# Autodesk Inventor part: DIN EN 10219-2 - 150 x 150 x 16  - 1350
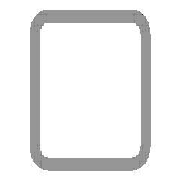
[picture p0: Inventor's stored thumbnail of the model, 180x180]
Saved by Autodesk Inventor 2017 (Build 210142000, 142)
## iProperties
_CCFamilyMember: 76
_CCFamilyDisplayName: DIN EN 10219-2 (Square Hollow Section - Cold Formed) - Cold formed welded structural hollow sections of non-alloy and fine grain structural steel
_FrameMemberDoc: Frame Member File
_Version: 15.0.0
_GetPNFromCC: 1
Created: 2017-11
Part Number: DIN EN 10219-2 - 150 x 150 x 16  - 1350
Material: Steel, Mild
Description: Cold formed welded structural hollow sections of non-alloy and fine grain structural steel
Document SubType Name: Modeling
Standard: DIN
Designer: iusti
Standard Revision: 2006-07
Standards Organization: DIN
Language: en-US
Size Designation: 150 x 150 x 16
Categories: <MemberInstance><Categories><Category DisplayName="Structural Shapes" InternalName="089c4875-fa83-4c05-b084-43b9cc11f5ed" Mnemonic="GRDR"><CategoryParameter Dis
Stock Number: 150 x 150 x 16
Mass: 79240 g
Surface Area: 12767.4 cm^2
Volume: 10094.3 cm^3
Density: 7.85 g/cm^3
Appearance: Semi-Polished
IsCustomPart: 1
G_L: 1350.000 mm
G_W: 150.000 mm
G_H: 150.000 mm
+6716C19D-968C-41AC-94F2-3194A5FEB298+CUTDETAIL1: Cut
+49856AF1-55B6-4B33-98D5-46D5E76A574D+CUTDETAIL2: Cut
Author: iusti
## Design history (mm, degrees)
node "Start plane"
node "End plane"
sketch "Sketch"
  geometry: L1 (-75, -27)-(-75, 27); L2 (-27, 75)-(27, 75); L3 (75, 27)-(75, -27); L4 (27, -75)-(-27, -75); L5 (-27, 59)-(27, 59); L6 (59, 27)-(59, -27); L7 (27, -59)-(-27, -59); L8 (-59, -27)-(-59, 27); L9 (0, 118.918)-(0, -118.918) reference; L10 (-118.918, 0)-(118.918, 0) reference; A1 r 48 centre (-27, -27) between (-75, -27) and (-27, -75); A2 r 48 centre (-27, 27) between (-27, 75) and (-75, 27); A3 r 48 centre (27, 27) between (75, 27) and (27, 75); A4 r 48 centre (27, -27) between (27, -75) and (75, -27); A5 r 32 centre (-27, 27) between (-27, 59) and (-59, 27); A6 r 32 centre (27, 27) between (59, 27) and (27, 59); A7 r 32 centre (27, -27) between (27, -59) and (59, -27); A8 r 32 centre (-27, -27) between (-59, -27) and (-27, -59)
  constraints: 16 end point, 16 point on circle, 8 centre point, 8 tangent, 4 parallel, 3 equal radius, 2 perpendicular, 7 other
  dimensions: "d7" = 48 radius of A1 (= G_IR); "d10" = 150 distance between parallel lines of L2 L4 (= G_H); "d11" = 150 distance between parallel lines of L1 L3 (= G_W); "d12" = 16 distance between parallel lines of L3 L6 (= G_T); "d15" = 75 distance between parallel lines of L2 L10 (= 0.5 x d10); "d16" = 75 distance between parallel lines of L9 L3 (= 0.5 x d11)
extrude "Body" new body sketch "Sketch" stored distance "d3" = 1350 (= G_L); taper "d4" = 0 deg
node "Driven Length"
  sketch "Sketch3"
    geometry: L1 (0, 0)-(10, 0) reference
    constraints: 2 end point, 1 horizontal
  workplane "Work Plane3"
  sketch "Sketch4"
    geometry: L1 (-2, 75)-(12, 75) reference; L2 (-2, 1425)-(12, 1425) reference
    dimensions: "d18" = 1350 distance between parallel lines of L1 L2 (derived)
workplane "Work Plane4"
split "Split1"
workplane "Work Plane5"
split "Split2"
body "Solid1"
other parameters: "G_W" = 150 [user parameter; used in 1 equation term], "G_H" = 150 [user parameter; used in 1 equation term], "G_T" = 16 [user parameter; used in 1 equation term], "G_IR" = 48 [user parameter; used in 1 equation term], "G_L" = 1350 (= d18) [user parameter; used in 1 equation term], "G_OFFSET_START" = -75 [user parameter; used in 1 equation term], "G_OFFSET_END" = -75 [user parameter; used in 1 equation term], "d13" = 75 (= -G_OFFSET_START), "d14" = 1425 (= G_OFFSET_END + B_L), "d17" = 90 deg
